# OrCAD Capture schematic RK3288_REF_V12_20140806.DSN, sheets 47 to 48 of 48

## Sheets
47 62.WIFI/BT/GPS-AP6476 (option): size A4; title: WIFI/BT/GPS-AP6476 (option); note: WIFI/BT/GPS-AP6476 (option)
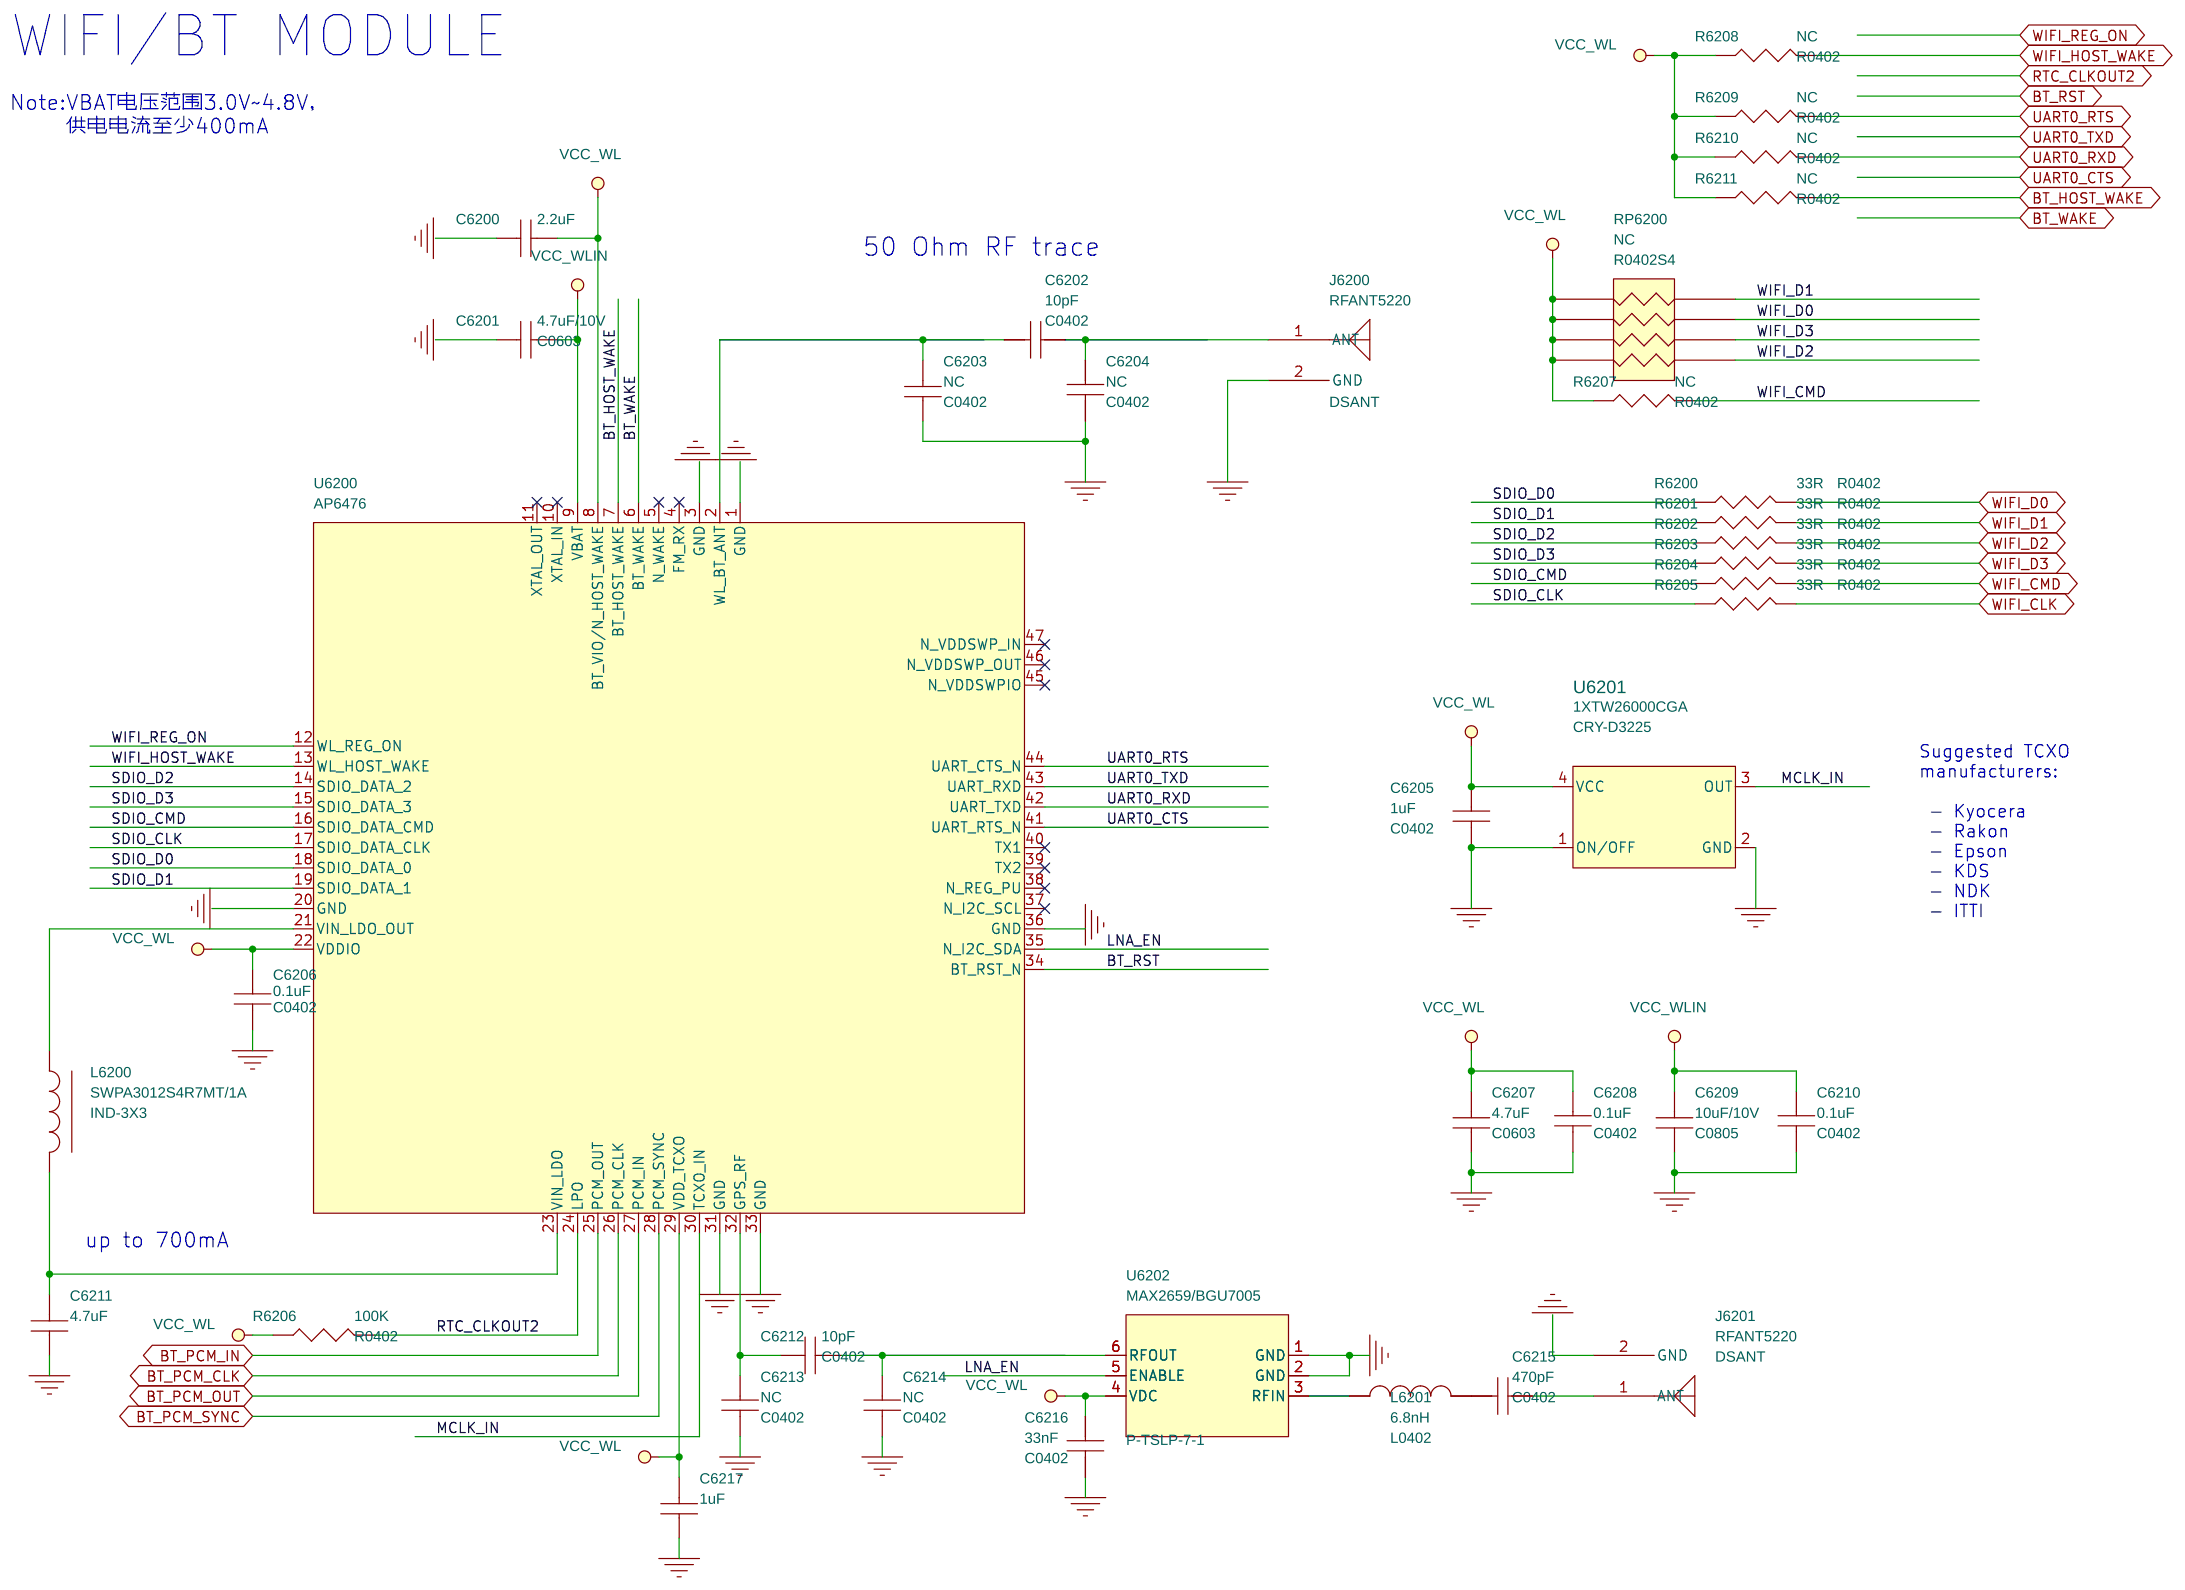
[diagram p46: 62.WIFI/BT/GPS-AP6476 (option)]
48 61.WIFI ac/BT-AP6335 (option): size A3; title: WIFI ac/BT-AP6335 (option); note: WIFI/BT/FM-AP6335 (option)
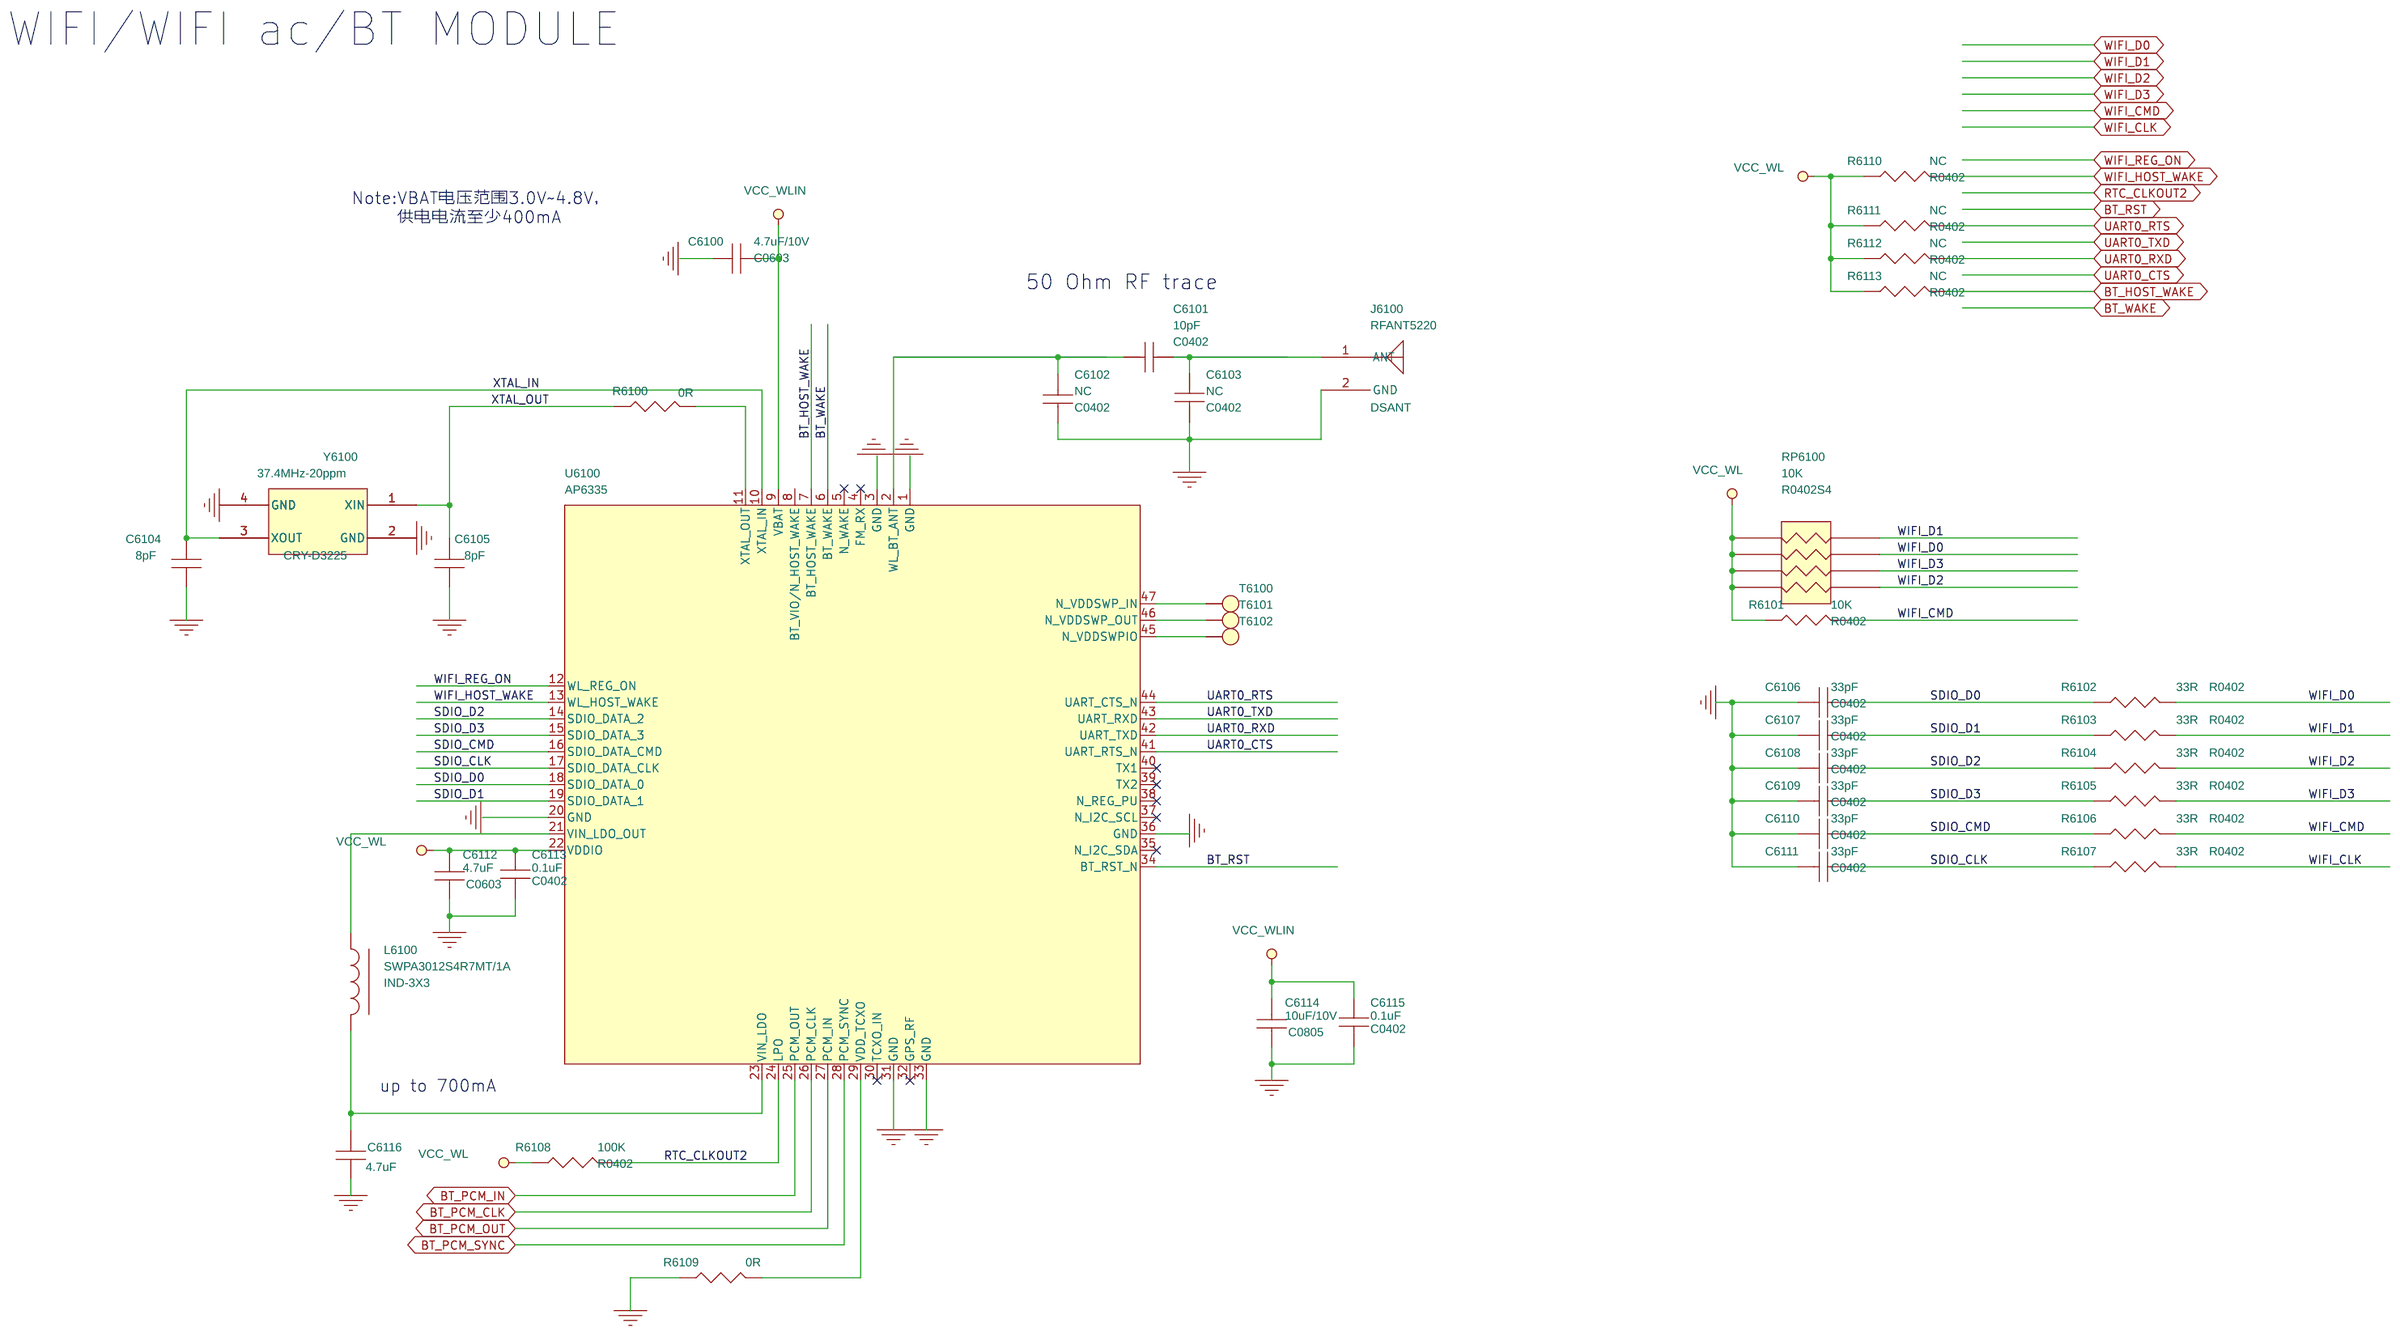
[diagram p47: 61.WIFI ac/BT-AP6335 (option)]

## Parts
sheet 61.WIFI ac/BT-AP6335 (option)
C6100  4.7uF/10V  [C0603]
C6101  10pF  [C0402]
C6102  NC  [C0402]
C6103  NC  [C0402]
C6104  8pF  [C0402]
C6105  8pF  [C0402]
C6106  33pF  [C0402]
C6107  33pF  [C0402]
C6108  33pF  [C0402]
C6109  33pF  [C0402]
C6110  33pF  [C0402]
C6111  33pF  [C0402]
C6112  4.7uF  [C0603]
C6113  0.1uF  [C0402]
C6114  10uF/10V  [C0805]
C6115  0.1uF  [C0402]
C6116  4.7uF  [C0603]
J6100  RFANT5220  [DSANT]
L6100  SWPA3012S4R7MT/1A  [IND-3X3]
R6100  0R  [R0402]
R6101  10K  [R0402]
R6102  33R  [R0402]
R6103  33R  [R0402]
R6104  33R  [R0402]
R6105  33R  [R0402]
R6106  33R  [R0402]
R6107  33R  [R0402]
R6108  100K  [R0402]
R6109  0R  [R0402]
R6110  NC  [R0402]
R6111  NC  [R0402]
R6112  NC  [R0402]
R6113  NC  [R0402]
RP6100  10K  [R0402S4]
T6100  TEST  [T-0.7]
T6101  TEST  [T-0.7]
T6102  TEST  [T-0.7]
U6100  AP6335  [AP6XXX]
Y6100  37.4MHz-20ppm  [CRY-D3225]
sheet 62.WIFI/BT/GPS-AP6476 (option)
C6200  2.2uF  [C0603]
C6201  4.7uF/10V  [C0603]
C6202  10pF  [C0402]
C6203  NC  [C0402]
C6204  NC  [C0402]
C6205  1uF  [C0402]
C6206  0.1uF  [C0402]
C6207  4.7uF  [C0603]
C6208  0.1uF  [C0402]
C6209  10uF/10V  [C0805]
C6210  0.1uF  [C0402]
C6211  4.7uF  [C0603]
C6212  10pF  [C0402]
C6213  NC  [C0402]
C6214  NC  [C0402]
C6215  470pF  [C0402]
C6216  33nF  [C0402]
C6217  1uF  [C0402]
J6200  RFANT5220  [DSANT]
J6201  RFANT5220  [DSANT]
L6200  SWPA3012S4R7MT/1A  [IND-3X3]
L6201  6.8nH  [L0402]
R6200  33R  [R0402]
R6201  33R  [R0402]
R6202  33R  [R0402]
R6203  33R  [R0402]
R6204  33R  [R0402]
R6205  33R  [R0402]
R6206  100K  [R0402]
R6207  NC  [R0402]
R6208  NC  [R0402]
R6209  NC  [R0402]
R6210  NC  [R0402]
R6211  NC  [R0402]
RP6200  NC  [R0402S4]
U6200  AP6476  [AP6XXX]
U6201  1XTW26000CGA  [CRY-D3225]
U6202  MAX2659/BGU7005  [P-TSLP-7-1]

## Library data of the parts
C6100 C6201 = CAP_NP: RoHS CHIP CAP 4.7uF +10/-10% X5R; BOM_TYPE: 20; BOM_VALUE: 0
C6101 C6102 C6202 C6203 = CAP_NP: RoHS CHIP CAP 10pF +10/-10% X7R; BOM_TYPE: 20; BOM_VALUE: 0
C6103 C6204 = CAP_NP: BOM_TYPE: 30; BOM_VALUE: 0
C6104 C6105 = CAP_NP: RoHS CHIP CAP 8pF +/-1% NPO; BOM_TYPE: 30; BOM_VALUE: 0
C6106-C6112 C6114 C6207 C6209 = CAP_NP: CAP,MLCC,10uF,+/-10%,X5R,6.3V,SMD0805
C6113 C6115 C6206 C6208 C6210 = CAP_NP: CAP,MLCC,100nF,+/-10%,X7R,6.3V,SMD0402
C6116 C6211 = CAP_NP: RoHS CHIP CAP 4.7uF +10/-10% X5R; BOM_TYPE: 30; BOM_VALUE: 0
J6100 J6200 J6201 = ANT3: ANT
L6100 L6200 = INDUCTORS_OF_FERRITE
R6100 = RES_1B: ROHS CHIP RES 470 Ohm 1/16W  +/-5%; BOM_TYPE: 20; BOM_VALUE: 0
R6101 R6110-R6113 R6207-R6211 = RESISTOR: ROHS CHIP RES 10K 1/16W +/-5%
R6102-R6107 R6200-R6205 = RESISTOR: RES,thick film,33Ohm,+/-5%,1/16W,SMD0402
R6108 R6206 = RESISTOR_0
R6109 = RESISTOR: ROHS CHIP RES 200 Ohm 1/16W +/-5%; BOM_TYPE: 20; BOM_VALUE: 0
RP6100 RP6200 = RESISTOR_4PACK: ROHS CHIP RES 10K 1/16W +/-5%
T6100-T6102 = TESTPOINT1
U6100 U6200 = WIFI-AP6XXX: WIFI&BT; BOM_TYPE: 10; BOM_VALUE: 8; Device: AMPAK_SIP; ORCAD_LIB: MODULE; QVL: AMPAK
Y6100 = CRYSTAL-4: Crystal,24.000MHz,+/-20ppm,12pF,SMD3225,-10°C ~ +60   °C; BOM_TYPE: 62; BOM_VALUE: 0
C6200 C6217 = CAP_NP: RoHS CHIP CAP 2.2uF +10/-10% X5R; BOM_TYPE: 30; BOM_VALUE: 0
C6205 C6212-C6214 = CAP_NP: RoHS CHIP CAP 2.2uF +10/-10% X5R
C6215 C6216 = CAP_NP
L6201 = INDUCTOR
U6201 = CRYSTAL_OSC: 1XTW26000CGA  KDS TCXO 26MHZ 1.8V 0.5PPM ,SMD3225
U6202 = LNA_MAX2659

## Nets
GND: C6100.1 C6102.1 C6103.2 C6104.1 C6105.1 C6106.2 C6107.2 C6108.2 C6109.2 C6110.2 C6111.2 C6112.1 C6113.2 C6114.1 C6115.2 C6116.1 C6200.1 C6201.1 C6203.1 C6204.2 C6205.2 C6206.2 C6207.1 C6208.2 C6209.1 C6210.2 C6211.1 C6213.2 C6214.2 C6216.2 C6217.1 J6100.2(GND) J6200.2(GND) J6201.2(GND) R6109.1 U6100.1(GND) U6100.3(GND) U6100.20(GND) U6100.31(GND) U6100.33(GND) U6100.36(GND) U6200.1(GND) U6200.3(GND) U6200.20(GND) U6200.31(GND) U6200.33(GND) U6200.36(GND) U6201.1(ON/OFF) U6201.2(GND) U6202.1(GND) U6202.2(GND) Y6100.2(GND) Y6100.4(GND) ; also on sheet 5 6 7 8 9 10 11 12 13 14 15 16 17 18 19 20 21 22 23 24 25 26 27 28 29 30 31 32 33 34 35 36 37 38 39 40 41 42 43 44 45 46
VCC_WL: C6112.2 C6113.1 C6200.2 C6205.1 C6206.1 C6207.2 C6208.1 C6216.1 C6217.2 R6101.1 R6108.1 R6110.1 R6111.1 R6112.1 R6113.1 R6206.1 R6207.1 R6208.1 R6209.1 R6210.1 R6211.1 RP6100.1 RP6100.2 RP6100.3 RP6100.4 RP6200.1 RP6200.2 RP6200.3 RP6200.4 U6100.22(VDDIO) U6200.8(BT_VIO/N_HOST_WAKE) U6200.22(VDDIO) U6200.29(VDD_TCXO) U6201.4(VCC) U6202.4(VDC) ; also on sheet 11 13 14 44
VCC_WLIN: C6100.2 C6114.2 C6115.1 C6201.2 C6209.2 C6210.1 U6100.9(VBAT) U6200.9(VBAT) ; also on sheet 13 14 44
BT_HOST_WAKE: R6113.2 R6211.2 U6100.7(BT_HOST_WAKE) U6200.7(BT_HOST_WAKE) ; also on sheet 11 44
BT_PCM_CLK: U6100.26(PCM_CLK) U6200.26(PCM_CLK) ; also on sheet 35 44
BT_PCM_IN: U6100.25(PCM_OUT) U6200.25(PCM_OUT) ; also on sheet 35 44
BT_PCM_OUT: U6100.27(PCM_IN) U6200.27(PCM_IN) ; also on sheet 35 44
BT_PCM_SYNC: U6100.28(PCM_SYNC) U6200.28(PCM_SYNC) ; also on sheet 35 44
BT_RST: U6100.34(BT_RST_N) U6200.34(BT_RST_N) ; also on sheet 11 44
BT_WAKE: U6100.6(BT_WAKE) U6200.6(BT_WAKE) ; also on sheet 11 44
LNA_EN: U6200.35(N_I2C_SDA) U6202.5(ENABLE)
MCLK_IN (page 62.WIFI/BT/GPS-AP6476 (option)): U6200.30(TCXO_IN) U6201.3(OUT)
RTC_CLKOUT2: R6108.2 R6206.2 U6100.24(LPO) U6200.24(LPO) ; also on sheet 13 14 44
SDIO_CLK (page 61.WIFI ac/BT-AP6335 (option)): C6111.1 R6107.1 U6100.17(SDIO_DATA_CLK)
SDIO_CLK (page 62.WIFI/BT/GPS-AP6476 (option)): R6205.1 U6200.17(SDIO_DATA_CLK)
SDIO_CMD (page 61.WIFI ac/BT-AP6335 (option)): C6110.1 R6106.1 U6100.16(SDIO_DATA_CMD)
SDIO_CMD (page 62.WIFI/BT/GPS-AP6476 (option)): R6204.1 U6200.16(SDIO_DATA_CMD)
SDIO_D0 (page 61.WIFI ac/BT-AP6335 (option)): C6106.1 R6102.1 U6100.18(SDIO_DATA_0)
SDIO_D0 (page 62.WIFI/BT/GPS-AP6476 (option)): R6200.1 U6200.18(SDIO_DATA_0)
SDIO_D1 (page 61.WIFI ac/BT-AP6335 (option)): C6107.1 R6103.1 U6100.19(SDIO_DATA_1)
SDIO_D1 (page 62.WIFI/BT/GPS-AP6476 (option)): R6201.1 U6200.19(SDIO_DATA_1)
SDIO_D2 (page 61.WIFI ac/BT-AP6335 (option)): C6108.1 R6104.1 U6100.14(SDIO_DATA_2)
SDIO_D2 (page 62.WIFI/BT/GPS-AP6476 (option)): R6202.1 U6200.14(SDIO_DATA_2)
SDIO_D3 (page 61.WIFI ac/BT-AP6335 (option)): C6109.1 R6105.1 U6100.15(SDIO_DATA_3)
SDIO_D3 (page 62.WIFI/BT/GPS-AP6476 (option)): R6203.1 U6200.15(SDIO_DATA_3)
UART0_CTS: U6100.41(UART_RTS_N) U6200.41(UART_RTS_N) ; also on sheet 11 44
UART0_RTS: R6111.2 R6209.2 U6100.44(UART_CTS_N) U6200.44(UART_CTS_N) ; also on sheet 11 44
UART0_RXD: R6112.2 R6210.2 U6100.42(UART_TXD) U6200.42(UART_TXD) ; also on sheet 11 44
UART0_TXD: U6100.43(UART_RXD) U6200.43(UART_RXD) ; also on sheet 11 44
WIFI_CLK: R6107.2 R6205.2 ; also on sheet 11 44
WIFI_CMD: R6101.2 R6106.2 R6204.2 R6207.2 ; also on sheet 11 44
WIFI_D0: R6102.2 R6200.2 RP6100.7 RP6200.7 ; also on sheet 11 44
WIFI_D1: R6103.2 R6201.2 RP6100.8 RP6200.8 ; also on sheet 11 44
WIFI_D2: R6104.2 R6202.2 RP6100.5 RP6200.5 ; also on sheet 11 44
WIFI_D3: R6105.2 R6203.2 RP6100.6 RP6200.6 ; also on sheet 11 44
WIFI_HOST_WAKE: R6110.2 R6208.2 U6100.13(WL_HOST_WAKE) U6200.13(WL_HOST_WAKE) ; also on sheet 11 44
WIFI_REG_ON: U6100.12(WL_REG_ON) U6200.12(WL_REG_ON) ; also on sheet 11 44
XTAL_IN (page 61.WIFI ac/BT-AP6335 (option)): C6104.2 U6100.10(XTAL_IN) Y6100.3(XOUT)
XTAL_OUT (page 61.WIFI ac/BT-AP6335 (option)): C6105.2 R6100.2 Y6100.1(XIN)
N59748653: R6109.2 U6100.29(VDD_TCXO)
N59749027: R6100.1 U6100.11(XTAL_OUT)
N59749300: T6102.1 U6100.45(N_VDDSWPIO)
N59749302: T6101.1 U6100.46(N_VDDSWP_OUT)
N59749304: T6100.1 U6100.47(N_VDDSWP_IN)
N61864678: L6201.1 U6202.3(RFIN)
N61864680: C6212.2 C6214.1 U6202.6(RFOUT)
N61865007: C6215.1 J6201.1(ANT)
N61865117: C6211.2 L6200.2 U6200.23(VIN_LDO)
N61865123: C6212.1 C6213.1 U6200.32(GPS_RF)
N61865141: C6202.1 C6204.1 J6200.1(ANT)
N61865423: C6202.2 C6203.2 U6200.2(WL_BT_ANT)
N61865527: L6200.1 U6200.21(VIN_LDO_OUT)
N62435739: C6116.2 L6100.2 U6100.23(VIN_LDO)
N62435742: C6101.2 C6102.2 U6100.2(WL_BT_ANT)
N62435744: C6101.1 C6103.1 J6100.1(ANT)
N62435762: L6100.1 U6100.21(VIN_LDO_OUT)
N64092795: C6215.2 L6201.2

Not connected (* = marked no-connect by the designer): U6100 4(FM_RX)* 5(N_WAKE)* 8(BT_VIO/N_HOST_WAKE) 30(TCXO_IN)* 32(GPS_RF)* 35(N_I2C_SDA)* 37(N_I2C_SCL)* 38(N_REG_PU)* 39(TX2)* 40(TX1)*; U6200 4(FM_RX)* 5(N_WAKE)* 10(XTAL_IN)* 11(XTAL_OUT)* 37(N_I2C_SCL)* 38(N_REG_PU)* 39(TX2)* 40(TX1)* 45(N_VDDSWPIO)* 46(N_VDDSWP_OUT)* 47(N_VDDSWP_IN)*

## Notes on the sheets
sheet 47
- WIFI/BT MODULE
- Note:VBAT电压范围3.0V~4.8V，
       供电电流至少400mA
- 50 Ohm RF trace
- Suggested TCXO
  manufacturers:
   - Kyocera
   - Rakon
   - Epson
   - KDS
   - NDK
   - ITTI
- up to 700mA
sheet 48
- WIFI/WIFI ac/BT MODULE
- Note:VBAT电压范围3.0V~4.8V，
       供电电流至少400mA
- 50 Ohm RF trace
- up to 700mA
